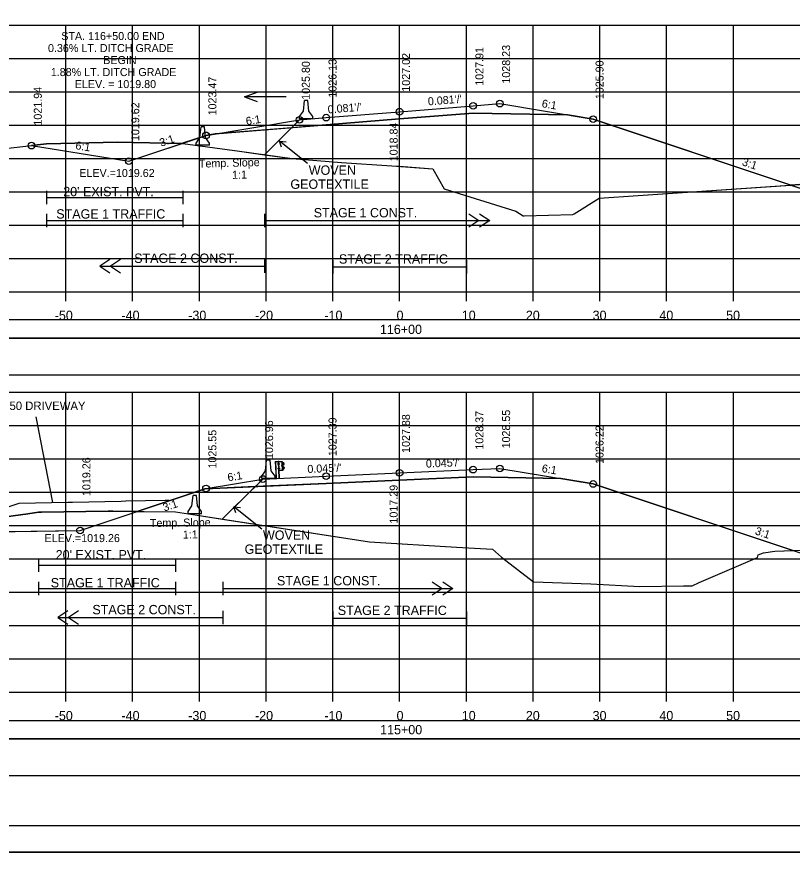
# Model space of a CAD drawing. Extents: x 1370565 to 1374448, y 301010 to 304637.
# Drawn here: x 1370677.7 to 1370793.8, y 302717.2 to 302842.4 of the extents above; entities that cross this region are included whole.
import ezdxf

# ---------------------------------------------------------------- set-up
doc = ezdxf.new("R2010")
doc.units = 0
for name, color, linetype in [('Default', 7, 'Continuous'), ('R_Alt Surface', 7, 'Continuous'), ('R_Axis', 7, 'Continuous'), ('R_Axis Annot', 7, 'Continuous'), ('R_Border', 7, 'Continuous'), ('R_Contours', 7, 'Continuous'), ('R_Drive', 7, 'Continuous'), ('R_Exist Surface', 7, 'Continuous'), ('R_Fin Surface', 7, 'Continuous'), ('R_Grid', 7, 'Continuous'), ('R_MOT', 7, 'Continuous'), ('R_No Plot', 7, 'Continuous'), ('R_Proposed Road', 7, 'Continuous'), ('R_Water', 7, 'Continuous'), ('R_Water Annot', 7, 'Continuous'), ('R_Xsect Elev', 7, 'Continuous'), ('R_Xsect Slope', 7, 'Continuous')]:
    doc.layers.add(name, color=color, linetype=linetype)

# ---------------------------------------------------------------- blocks, each defined once
blk = doc.blocks.new('MEDBAR_P')
at = {"layer": 'R_MOT'}
for p, q in [((-2.46, -0.98), (-1.63, 6.93)), ((-0.38, 6.93), (-1.63, 6.93)), ((0.87, 6.93), (-0.38, 6.93)), ((1.71, -0.98), (0.87, 6.93)), ((-5.37, -6.81), (-5.34, -5.15)), ((-5.34, -5.15), (-2.46, -0.98)), ((4.66, -5.15), (1.71, -0.98)), ((4.63, -6.81), (4.66, -5.15)), ((4.63, -6.81), (-5.37, -6.81))]:
    blk.add_line(p, q, dxfattribs=at)
blk = doc.blocks.new('GUARDRAIL LT_P')
at = {"layer": 'R_Proposed Road'}
for p, q in [((0, 2.52), (0, 0)), ((0.03, 2.52), (0.03, 0)), ((0.53, 2.52), (0.46, 2.51)), ((0.49, 0), (0.49, 2.52)), ((0.53, 2.52), (0.52, 2.52)), ((1.02, 1.15), (1.02, 2.51)), ((0.39, 1.42), (0.39, 1.51)), ((0.4, 2.11), (0.4, 2.2)), ((0.45, 1.53), (0.4, 1.53)), ((0.45, 1.49), (0.4, 1.49)), ((0.45, 1.43), (0.4, 1.43)), ((0.45, 1.43), (0.4, 1.43)), ((0.45, 1.4), (0.4, 1.4)), ((0.46, 2.21), (0.41, 2.21)), ((0.46, 2.18), (0.41, 2.18)), ((0.46, 2.12), (0.41, 2.12)), ((0.46, 2.12), (0.41, 2.12)), ((0.46, 2.09), (0.41, 2.09)), ((0.45, 1.4), (0.45, 1.53)), ((0.46, 2.09), (0.46, 2.21)), ((0.58, 2.15), (0.52, 2.15)), ((0.58, 1.46), (0.52, 1.46)), ((0.53, 2.21), (0.58, 2.21)), ((0.53, 2.08), (0.58, 2.08)), ((0.58, 1.53), (0.53, 1.53)), ((0.58, 1.4), (0.53, 1.4)), ((0.58, 2.21), (0.58, 2.08)), ((0.58, 1.4), (0.58, 1.53)), ((1.01, 1.89), (0.96, 1.89)), ((0.96, 1.78), (0.96, 1.88)), ((1.01, 1.86), (0.96, 1.86)), ((1.01, 1.8), (0.96, 1.8)), ((1.01, 1.77), (0.96, 1.77)), ((1.01, 1.8), (0.97, 1.8)), ((1.01, 1.77), (1.01, 1.89)), ((1.05, 1.31), (1.16, 1.37)), ((1.17, 2.3), (1.06, 2.36)), ((1.16, 2.29), (1.06, 2.34)), ((1.06, 1.77), (1.06, 1.9)), ((1.06, 1.29), (1.17, 1.35)), ((1.09, 1.77), (1.09, 1.9)), ((1.26, 1.6), (1.1, 1.69)), ((1.11, 1.97), (1.28, 2.07)), ((1.12, 1.95), (1.29, 2.05)), ((1.27, 1.62), (1.12, 1.71)), ((1.28, 2.18), (1.16, 2.29)), ((1.16, 1.37), (1.29, 1.48)), ((1.3, 2.2), (1.17, 2.3)), ((1.17, 1.35), (1.3, 1.46)), ((0.52, 1.15), (0.49, 1.15))]:
    blk.add_line(p, q, dxfattribs=at)
blk.add_lwpolyline([(0, 2.52), (0.46, 2.51), (0.45, 0)], dxfattribs=at)
for points in [[(1.05, 2.52), (1.05, 1.15), (0.52, 1.15), (0.53, 2.52)], [(0.39, 1.49), (0.39, 1.43), (0.36, 1.43), (0.36, 1.49)], [(0.4, 2.18), (0.4, 2.12), (0.37, 2.12), (0.37, 2.18)], [(0.44, 1.55), (0.44, 1.38), (0.45, 1.38), (0.45, 1.55)], [(0.45, 2.23), (0.45, 2.07), (0.46, 2.07), (0.46, 2.23)], [(0.58, 2.21), (0.58, 2.08), (0.53, 2.08), (0.53, 2.21)], [(0.58, 1.53), (0.58, 1.4), (0.53, 1.4), (0.53, 1.53)], [(0.95, 1.86), (0.95, 1.8), (0.93, 1.8), (0.93, 1.86)], [(1.01, 1.91), (1.01, 1.75), (1.02, 1.75), (1.02, 1.91)]]:
    blk.add_lwpolyline(points, close=True, dxfattribs=at)
for centre, radius, start, end in [((0.41, 1.51), 0.022, 134.5745, 222.2244), ((0.48, 1.46), 0.0922, 159.7423, 200.2577), ((0.41, 1.41), 0.025, 140.9334, 216.6234), ((0.42, 2.2), 0.022, 134.5745, 222.2244), ((0.49, 2.15), 0.0922, 159.7423, 200.2577), ((0.43, 2.1), 0.025, 140.9334, 216.6234), ((0.98, 1.88), 0.022, 134.5745, 222.2244), ((1.05, 1.83), 0.0922, 159.7423, 200.2577), ((0.98, 1.78), 0.025, 140.9334, 216.6234), ((1.15, 1.89), 0.0865, 118.106, 175.0444), ((1.13, 1.76), 0.0703, 171.7804, 246.8536), ((1.08, 1.83), 0.0453, 282.9554, 86.0697), ((1.15, 1.89), 0.0622, 118.106, 175.0444), ((1.13, 1.76), 0.0462, 171.7804, 246.8536), ((1.22, 1.52), 0.0854, 325.2184, 59.12), ((1.22, 1.52), 0.109, 325.2184, 59.12), ((1.25, 2.13), 0.062, 299.2499, 57.9783), ((1.25, 2.13), 0.0856, 299.2499, 57.9783)]:
    blk.add_arc(centre, radius, start, end, dxfattribs=at)

msp = doc.modelspace()

# ---------------------------------------------------------------- linework, layer by layer
at = {"layer": 'Default'}
for points in [[(1370585.82, 302788.75), (1370884.24, 302788.75), (1370884.24, 302794.27), (1370585.82, 302794.27)], [(1370585.82, 302728.7), (1370884.24, 302728.7), (1370884.24, 302734.22), (1370585.82, 302734.22)]]:
    msp.add_lwpolyline(points, close=True, dxfattribs=at)
at = {"layer": 'R_Alt Surface'}
for points in [[(1370707.4, 302824.88), (1370724.03, 302826.22), (1370735.03, 302827.11), (1370746.03, 302828), (1370760.16, 302827.72)], [(1370721.23, 302820.42), (1370717.05, 302823.77)], [(1370717.34, 302822.87), (1370717.05, 302823.77), (1370718.04, 302823.68)], [(1370714.8, 302812.89), (1370714.8, 302810.89)], [(1370745.42, 302812.89), (1370746.92, 302811.89), (1370745.42, 302810.89)], [(1370747.02, 302812.89), (1370748.52, 302811.89), (1370747.02, 302810.89)], [(1370714.8, 302811.89), (1370748.52, 302811.89)], [(1370691.62, 302806.07), (1370690.12, 302805.07), (1370691.62, 302804.07)], [(1370693.22, 302806.07), (1370691.72, 302805.07), (1370693.22, 302804.07)], [(1370714.8, 302806.07), (1370714.8, 302804.07)], [(1370725.03, 302805.95), (1370725.03, 302803.95)], [(1370745.03, 302805.95), (1370745.03, 302803.95)], [(1370690.12, 302805.07), (1370714.8, 302805.07)], [(1370725.03, 302804.95), (1370745.03, 302804.95)], [(1370705.86, 302771.67), (1370724.03, 302772.48), (1370735.03, 302772.98), (1370746.03, 302773.47), (1370759.18, 302773.21)], [(1370714.38, 302765.61), (1370710.2, 302768.96)], [(1370710.49, 302768.06), (1370710.2, 302768.96), (1370711.19, 302768.87)], [(1370708.53, 302757.73), (1370708.53, 302755.73)], [(1370739.92, 302757.73), (1370741.42, 302756.73), (1370739.92, 302755.73)], [(1370741.52, 302757.73), (1370743.02, 302756.73), (1370741.52, 302755.73)], [(1370708.53, 302756.73), (1370743.02, 302756.73)], [(1370685.35, 302753.39), (1370683.85, 302752.39), (1370685.35, 302751.39)], [(1370686.95, 302753.39), (1370685.45, 302752.39), (1370686.95, 302751.39)], [(1370708.53, 302753.39), (1370708.53, 302751.39)], [(1370725.03, 302753.28), (1370725.03, 302751.28)], [(1370745.03, 302753.28), (1370745.03, 302751.28)], [(1370683.85, 302752.39), (1370708.53, 302752.39)], [(1370725.03, 302752.28), (1370745.03, 302752.28)]]:
    msp.add_lwpolyline(points, dxfattribs=at)
at = {"layer": 'R_Axis'}
for p, q in [((1370585.03, 302801.18), (1370885.03, 302801.18)), ((1370685.03, 302799.78), (1370685.03, 302801.18)), ((1370695.03, 302799.78), (1370695.03, 302801.18)), ((1370705.03, 302799.78), (1370705.03, 302801.18)), ((1370715.03, 302799.78), (1370715.03, 302801.18)), ((1370725.03, 302799.78), (1370725.03, 302801.18)), ((1370735.03, 302799.78), (1370735.03, 302801.18)), ((1370745.03, 302799.78), (1370745.03, 302801.18)), ((1370755.03, 302799.78), (1370755.03, 302801.18)), ((1370765.03, 302799.78), (1370765.03, 302801.18)), ((1370775.03, 302799.78), (1370775.03, 302801.18)), ((1370785.03, 302799.78), (1370785.03, 302801.18)), ((1370585.03, 302741.18), (1370885.03, 302741.18)), ((1370685.03, 302739.78), (1370685.03, 302741.18)), ((1370695.03, 302739.78), (1370695.03, 302741.18)), ((1370705.03, 302739.78), (1370705.03, 302741.18)), ((1370715.03, 302739.78), (1370715.03, 302741.18)), ((1370725.03, 302739.78), (1370725.03, 302741.18)), ((1370735.03, 302739.78), (1370735.03, 302741.18)), ((1370745.03, 302739.78), (1370745.03, 302741.18)), ((1370755.03, 302739.78), (1370755.03, 302741.18)), ((1370765.03, 302739.78), (1370765.03, 302741.18)), ((1370775.03, 302739.78), (1370775.03, 302741.18)), ((1370785.03, 302739.78), (1370785.03, 302741.18))]:
    msp.add_line(p, q, dxfattribs=at)
for points in [[(1370682.14, 302816.33), (1370682.14, 302814.33)], [(1370702.54, 302816.33), (1370702.54, 302814.33)], [(1370682.14, 302815.33), (1370702.54, 302815.33)], [(1370682.14, 302812.89), (1370682.14, 302810.89)], [(1370702.54, 302812.89), (1370702.54, 302810.89)], [(1370682.14, 302811.89), (1370702.54, 302811.89)], [(1370680.94, 302761.25), (1370680.94, 302759.25)], [(1370701.47, 302761.25), (1370701.47, 302759.25)], [(1370680.94, 302760.25), (1370701.47, 302760.25)], [(1370680.94, 302757.73), (1370680.94, 302755.73)], [(1370701.47, 302757.73), (1370701.47, 302755.73)], [(1370680.94, 302756.73), (1370701.47, 302756.73)]]:
    msp.add_lwpolyline(points, dxfattribs=at)
at = {"layer": 'R_Border'}
msp.add_line((1370893.21, 302721.18), (1370577.03, 302721.18), dxfattribs=at)
at = {"layer": 'R_Contours'}
for p, q in [((1370718.85, 302825.8), (1370707.4, 302824.88)), ((1370718.85, 302825.8), (1370714.8, 302821.76)), ((1370714.8, 302821.76), (1370718.85, 302825.8)), ((1370702.39, 302823.44), (1370695.14, 302823.58)), ((1370793.61, 302817.21), (1370809.69, 302811.85)), ((1370713.37, 302772.01), (1370706.03, 302771.68)), ((1370713.37, 302772.01), (1370708.53, 302767.24)), ((1370708.53, 302767.24), (1370713.37, 302772.01)), ((1370706.03, 302771.68), (1370705.86, 302771.67))]:
    msp.add_line(p, q, dxfattribs=at)
for points in [[(1370760.16, 302827.72), (1370746.03, 302828), (1370735.03, 302827.11), (1370724.03, 302826.22), (1370718.85, 302825.8)], [(1370793.61, 302817.21), (1370764.03, 302827.08), (1370760.16, 302827.72)], [(1370707.4, 302824.88), (1370706.03, 302824.65), (1370702.52, 302823.48)], [(1370695.14, 302823.58), (1370692.71, 302823.63), (1370684.26, 302823.41), (1370682.14, 302823.37), (1370679.88, 302823.12)], [(1370679.88, 302823.12), (1370694.48, 302820.8), (1370702.39, 302823.44)], [(1370702.52, 302823.48), (1370702.54, 302823.43)], [(1370702.54, 302823.43), (1370711.03, 302822.29), (1370714.8, 302821.76)], [(1370714.8, 302821.76), (1370718.95, 302821.18), (1370726.31, 302820.58), (1370733.84, 302820.11), (1370735.03, 302820.02), (1370740.02, 302819.65), (1370741.69, 302816.66), (1370752.44, 302813.27), (1370753.52, 302812.6), (1370753.68, 302812.61), (1370760.98, 302812.78), (1370761.16, 302812.91), (1370764.9, 302815.23), (1370770.74, 302815.65), (1370793.61, 302817.21)], [(1370842.81, 302818.89), (1370842.28, 302818.87), (1370831.68, 302818.84), (1370825.97, 302818.74), (1370819.02, 302818.74), (1370816.76, 302818.69), (1370809.15, 302818.52), (1370795.82, 302817.37), (1370795.67, 302817.35), (1370793.61, 302817.21)], [(1370759.18, 302773.21), (1370746.03, 302773.47), (1370735.03, 302772.98), (1370724.03, 302772.48), (1370713.37, 302772.01)], [(1370793.95, 302762.43), (1370764.03, 302772.4), (1370759.18, 302773.21)], [(1370705.86, 302771.67), (1370700.53, 302769.89), (1370695.74, 302768.3)], [(1370665.04, 302765.11), (1370687.16, 302765.44), (1370695.74, 302768.3)], [(1370695.74, 302768.3), (1370692.06, 302768.34), (1370691.35, 302768.34), (1370681.39, 302768.17), (1370680.94, 302768.16), (1370679.32, 302767.95), (1370669.01, 302766.52)], [(1370695.74, 302768.3), (1370701.47, 302768.23), (1370704.7, 302767.74), (1370708.52, 302767.15)], [(1370708.53, 302767.24), (1370708.52, 302767.15)], [(1370708.52, 302767.15), (1370708.53, 302767.24)], [(1370708.52, 302767.15), (1370730.54, 302763.74), (1370743.57, 302762.94), (1370748.95, 302762.62), (1370750.3, 302761.45), (1370755.1, 302757.74), (1370763.65, 302757.42), (1370771.02, 302757.03), (1370777.53, 302757.13), (1370778.87, 302757.15), (1370779.9, 302757.61), (1370788.63, 302761.4), (1370788.72, 302761.79), (1370789.56, 302762.1), (1370791.22, 302762.31), (1370793.95, 302762.43)]]:
    msp.add_lwpolyline(points, dxfattribs=at)
at = {"layer": 'R_Drive'}
for points in [[(1370585.82, 302794.27), (1370884.24, 302794.27), (1370884.24, 302796.98), (1370585.82, 302796.98)], [(1370585.82, 302734.22), (1370884.24, 302734.22), (1370884.24, 302736.92), (1370585.82, 302736.92)]]:
    msp.add_lwpolyline(points, close=True, dxfattribs=at)
msp.add_lwpolyline([(1370665.04, 302765.2), (1370666.19, 302765.58), (1370678.03, 302769.53), (1370685.32, 302769.68), (1370686.03, 302769.69), (1370693.32, 302769.84), (1370694.03, 302769.85), (1370699.9, 302769.97), (1370700.51, 302769.98)], dxfattribs=at)
at = {"layer": 'R_Exist Surface'}
for points in [[(1370673.69, 302822.45), (1370682.14, 302823.37), (1370684.26, 302823.41), (1370692.71, 302823.63), (1370695.14, 302823.58), (1370702.54, 302823.43), (1370711.03, 302822.29), (1370718.95, 302821.18), (1370726.31, 302820.58), (1370733.84, 302820.11), (1370740.02, 302819.65), (1370741.69, 302816.66), (1370752.44, 302813.27), (1370752.44, 302813.27), (1370753.52, 302812.6), (1370753.68, 302812.61), (1370760.98, 302812.78), (1370761.16, 302812.91), (1370764.9, 302815.23), (1370770.74, 302815.65), (1370795.67, 302817.35)], [(1370655.24, 302764.63), (1370679.32, 302767.95), (1370680.94, 302768.16), (1370681.39, 302768.17), (1370691.35, 302768.34), (1370692.06, 302768.34), (1370701.47, 302768.23), (1370704.7, 302767.74), (1370730.54, 302763.74), (1370743.57, 302762.94), (1370748.95, 302762.62), (1370750.3, 302761.45), (1370755.1, 302757.74), (1370763.65, 302757.42), (1370771.02, 302757.03), (1370777.53, 302757.13), (1370778.87, 302757.15), (1370779.9, 302757.61), (1370788.63, 302761.4), (1370788.72, 302761.79), (1370789.56, 302762.1), (1370791.22, 302762.31), (1370796.92, 302762.55)]]:
    msp.add_lwpolyline(points, dxfattribs=at)
at = {"layer": 'R_Fin Surface'}
for p, q in [((1370720.03, 302826.98), (1370714.8, 302821.76)), ((1370714.53, 302773.14), (1370708.53, 302767.24))]:
    msp.add_line(p, q, dxfattribs=at)
for points in [[(1370679.88, 302823.12), (1370694.48, 302820.8), (1370706.03, 302824.65), (1370720.03, 302826.98), (1370724.03, 302827.31), (1370735.03, 302828.2), (1370746.03, 302829.09), (1370750.03, 302829.41), (1370764.03, 302827.08), (1370809.69, 302811.85), (1370821.69, 302811.85), (1370842.81, 302818.89)], [(1370657.93, 302765), (1370687.16, 302765.44), (1370706.03, 302771.72), (1370714.53, 302773.14), (1370724.03, 302773.57), (1370735.03, 302774.06), (1370746.03, 302774.55), (1370750.03, 302774.73), (1370764.03, 302772.4), (1370813.59, 302755.88), (1370825.59, 302755.88), (1370848.25, 302763.43)]]:
    msp.add_lwpolyline(points, dxfattribs=at)
at = {"layer": 'R_Grid'}
for p, q in [((1370585.03, 302841.18), (1370885.03, 302841.18)), ((1370685.03, 302801.18), (1370685.03, 302841.18)), ((1370695.03, 302801.18), (1370695.03, 302841.18)), ((1370705.03, 302801.18), (1370705.03, 302841.18)), ((1370715.03, 302801.18), (1370715.03, 302841.18)), ((1370725.03, 302801.18), (1370725.03, 302841.18)), ((1370735.03, 302801.18), (1370735.03, 302841.18)), ((1370745.03, 302801.18), (1370745.03, 302841.18)), ((1370755.03, 302801.18), (1370755.03, 302841.18)), ((1370765.03, 302801.18), (1370765.03, 302841.18)), ((1370775.03, 302801.18), (1370775.03, 302841.18)), ((1370785.03, 302801.18), (1370785.03, 302841.18)), ((1370585.03, 302836.18), (1370885.03, 302836.18)), ((1370585.03, 302831.18), (1370885.03, 302831.18)), ((1370585.03, 302826.18), (1370885.03, 302826.18)), ((1370585.03, 302821.18), (1370885.03, 302821.18)), ((1370585.03, 302816.18), (1370885.03, 302816.18)), ((1370585.03, 302811.18), (1370885.03, 302811.18)), ((1370585.03, 302806.18), (1370885.03, 302806.18)), ((1370585.03, 302801.18), (1370885.03, 302801.18)), ((1370585.03, 302786.18), (1370885.03, 302786.18)), ((1370685.03, 302741.18), (1370685.03, 302786.18)), ((1370695.03, 302741.18), (1370695.03, 302786.18)), ((1370705.03, 302741.18), (1370705.03, 302786.18)), ((1370715.03, 302741.18), (1370715.03, 302786.18)), ((1370725.03, 302741.18), (1370725.03, 302786.18)), ((1370735.03, 302741.18), (1370735.03, 302786.18)), ((1370745.03, 302741.18), (1370745.03, 302786.18)), ((1370755.03, 302741.18), (1370755.03, 302786.18)), ((1370765.03, 302741.18), (1370765.03, 302786.18)), ((1370775.03, 302741.18), (1370775.03, 302786.18)), ((1370785.03, 302741.18), (1370785.03, 302786.18)), ((1370585.03, 302781.18), (1370885.03, 302781.18)), ((1370585.03, 302776.18), (1370885.03, 302776.18)), ((1370585.03, 302771.18), (1370885.03, 302771.18)), ((1370585.03, 302766.18), (1370885.03, 302766.18)), ((1370585.03, 302761.18), (1370885.03, 302761.18)), ((1370585.03, 302756.18), (1370885.03, 302756.18)), ((1370585.03, 302751.18), (1370885.03, 302751.18)), ((1370585.03, 302746.18), (1370885.03, 302746.18)), ((1370585.03, 302741.18), (1370885.03, 302741.18))]:
    msp.add_line(p, q, dxfattribs=at)
at = {"layer": 'R_No Plot'}
msp.add_line((1370564.63, 302717.2), (1370897.96, 302717.2), dxfattribs=at)
for points in [[(1370564.62, 302930.53), (1370897.96, 302930.53), (1370897.96, 302717.2), (1370564.62, 302717.2)], [(1370810.95, 302926.64), (1370830.57, 302926.64), (1370830.57, 302916.76), (1370846.68, 302916.76), (1370869.88, 302916.76), (1370869.88, 302884.09), (1370893.09, 302884.09), (1370893.21, 302721.18), (1370577.03, 302721.18), (1370577.03, 302926.64)]]:
    msp.add_lwpolyline(points, close=True, dxfattribs=at)
for centre in [(1370750.03, 302829.41), (1370735.03, 302828.2), (1370746.03, 302829.09), (1370720.03, 302826.98), (1370724.03, 302827.31), (1370764.03, 302827.08), (1370706.03, 302824.65), (1370679.88, 302823.12), (1370694.48, 302820.8), (1370735.03, 302774.06), (1370746.03, 302774.55), (1370750.03, 302774.73), (1370714.53, 302773.14), (1370724.03, 302773.57), (1370706.03, 302771.72), (1370764.03, 302772.4), (1370687.16, 302765.44)]:
    msp.add_circle(centre, 0.5, dxfattribs=at)
at = {"layer": 'R_Water Annot'}
for p, q in [((1370711.77, 302830.44), (1370713.7, 302831.14)), ((1370718.06, 302830.44), (1370711.77, 302830.44)), ((1370711.77, 302830.44), (1370713.7, 302829.74)), ((1370680.55, 302782.45), (1370683.02, 302769.63))]:
    msp.add_line(p, q, dxfattribs=at)
at = {"layer": 'R_Xsect Elev'}
for p, q in [((1370735.03, 302820.02), (1370735.03, 302826.4)), ((1370735.03, 302763.47), (1370735.03, 302772.43))]:
    msp.add_line(p, q, dxfattribs=at)

# ---------------------------------------------------------------- block references
at = {"layer": 'Default', "rotation": 2.60052997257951}
msp.add_blockref('GUARDRAIL LT_P', (1370716.52, 302773.23), dxfattribs=at)
at = {"layer": 'R_Fin Surface', "xscale": 0.2, "yscale": 0.20000000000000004}
for p in [(1370721.1, 302828.5), (1370705.61, 302824.53), (1370715.44, 302774.58), (1370704.42, 302769.31)]:
    msp.add_blockref('MEDBAR_P', p, dxfattribs=at)

# ---------------------------------------------------------------- texts
at = {"layer": 'R_Axis Annot'}
for s, p in [('WOVEN ', (1370721.42, 302818.74)), ('GEOTEXTILE', (1370718.67, 302816.64)), ("20' EXIST. PVT.", (1370684.64, 302815.53)), ('-50', (1370683.37, 302796.98)), ('-40', (1370693.37, 302796.98)), ('-30', (1370703.37, 302796.98)), ('-20', (1370713.37, 302796.98)), ('-10', (1370723.76, 302796.98)), ('0', (1370734.57, 302796.98)), ('10', (1370744.34, 302796.98)), ('20', (1370753.94, 302796.98)), ('30', (1370763.94, 302796.98)), ('40', (1370773.94, 302796.98)), ('50', (1370783.94, 302796.98)), ('116+00', (1370732.08, 302794.88)), ('WOVEN ', (1370714.56, 302764.03)), ('GEOTEXTILE', (1370711.81, 302761.93)), ("20' EXIST. PVT.", (1370683.51, 302761.1)), ('-50', (1370683.37, 302736.98)), ('-40', (1370693.37, 302736.98)), ('-30', (1370703.37, 302736.98)), ('-20', (1370713.37, 302736.98)), ('-10', (1370723.76, 302736.98)), ('0', (1370734.57, 302736.98)), ('10', (1370744.34, 302736.98)), ('20', (1370753.94, 302736.98)), ('30', (1370763.94, 302736.98)), ('40', (1370773.94, 302736.98)), ('50', (1370783.94, 302736.98)), ('115+00', (1370732.11, 302734.88))]:
    msp.add_text(s, height=1.4, dxfattribs=at).set_placement(p)
at = {"layer": 'R_Water'}
for s, p in [('STAGE 1 TRAFFIC', (1370683.6, 302812.18)), ('STAGE 1 CONST.', (1370722.16, 302812.36)), ('STAGE 2 CONST.', (1370695.27, 302805.54)), ('STAGE 2 TRAFFIC', (1370725.94, 302805.43)), ('STAGE 1 TRAFFIC', (1370682.77, 302756.9)), ('STAGE 1 CONST.', (1370716.66, 302757.2)), ('STAGE 2 CONST.', (1370689.01, 302752.87)), ('STAGE 2 TRAFFIC', (1370725.77, 302752.76))]:
    msp.add_text(s, height=1.4, dxfattribs=at).set_placement(p)
at = {"layer": 'R_Water Annot'}
msp.add_text('115+50 DRIVEWAY', height=1.2661, dxfattribs=at).set_placement((1370672.78, 302783.49))
at = {"layer": 'R_Xsect Elev'}
for s, p in [('STA. 116+50.00 END', (1370684.35, 302838.94)), ('0.36% LT. DITCH GRADE', (1370682.36, 302837.14)), ('BEGIN', (1370690.64, 302835.34)), ('1.88% LT. DITCH GRADE', (1370682.78, 302833.54)), ('ELEV. = 1019.80', (1370686.37, 302831.74)), ('ELEV.=1019.62', (1370687.05, 302818.41)), ('ELEV.=1019.26', (1370681.84, 302763.69))]:
    msp.add_text(s, height=1.2, dxfattribs=at).set_placement(p)
for s, p in [('1027.91', (1370747.58, 302832.09)), ('1028.23', (1370751.58, 302832.41)), ('1026.13', (1370725.58, 302830.31)), ('1027.02', (1370736.58, 302831.2)), ('1025.80', (1370721.58, 302829.98)), ('1025.90', (1370765.58, 302830.08)), ('1023.47', (1370707.58, 302827.65)), ('1021.94', (1370681.43, 302826.12)), ('1019.62', (1370696.03, 302823.8)), ('1018.84', (1370734.73, 302820.77)), ('1028.37', (1370747.58, 302777.55)), ('1028.55', (1370751.58, 302777.73)), ('1027.39', (1370725.58, 302776.57)), ('1027.88', (1370736.58, 302777.06)), ('1026.96', (1370716.08, 302776.14)), ('1026.22', (1370765.58, 302775.4)), ('1025.55', (1370707.58, 302774.72)), ('1019.26', (1370688.71, 302770.6)), ('1017.29', (1370734.73, 302766.47))]:
    msp.add_text(s, height=1.2, rotation=90, dxfattribs=at).set_placement(p)
at = {"layer": 'R_Xsect Slope'}
for s, rotation, p in [("0.081'/'", 4.623, (1370739.31, 302829.14)), ('6:1', 350.5377, (1370756.26, 302828.88)), ("0.081'/'", 4.6231, (1370724.31, 302827.93)), ('6:1', 9.4623, (1370712.1, 302826.17)), ('3:1', 18.4349, (1370699.3, 302822.94)), ('6:1', 350.9572, (1370686.41, 302822.59)), ('Temp. Slope ', 1.4768, (1370704.98, 302819.81)), ('3:1', 341.5651, (1370786.23, 302820.2)), ('1:1', 1.4768, (1370709.95, 302818.13)), ("0.045'/'", 2.5687, (1370738.99, 302774.84)), ("0.045'/'", 2.5688, (1370721.24, 302774.04)), ('6:1', 350.5377, (1370756.26, 302774.2)), ('6:1', 9.4623, (1370709.35, 302772.78)), ('3:1', 18.4349, (1370699.79, 302768.26)), ('Temp. Slope ', 0.826, (1370697.63, 302765.94)), ('3:1', 341.5651, (1370788.18, 302764.88)), ('1:1', 0.826, (1370702.57, 302764.22))]:
    msp.add_text(s, height=1.2, rotation=rotation, dxfattribs=at).set_placement(p)

doc.saveas('drawing.dxf')
